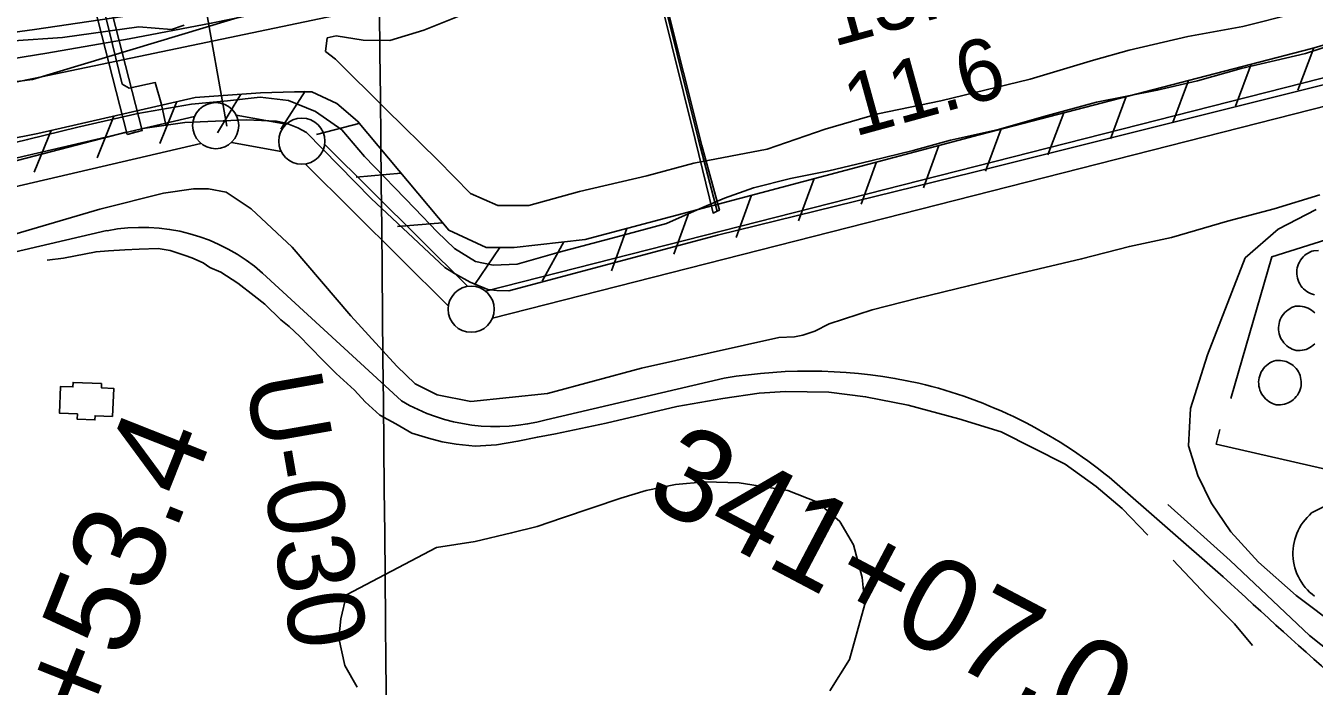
# Model space of a CAD drawing. Extents: x 3625074 to 3663148, y 511451 to 537151.
# Drawn here: x 3639466 to 3640863, y 517652 to 518368 of the extents above; entities that cross this region are included whole.
import ezdxf

# ---------------------------------------------------------------- set-up
doc = ezdxf.new("R2010")
doc.units = 0
for name, color, linetype in [('V-BLDG-OTLN', 7, 'Continuous'), ('V-CHAN-DOCK', 7, 'Continuous'), ('V-DOMW-TANK', 7, 'Continuous'), ('V-FLOD-BASE', 7, 'Continuous'), ('V-GRID-MAJR', 7, 'Continuous'), ('V-LEVE-TOET', 7, 'Continuous'), ('V-RIVR-EDGE', 7, 'Continuous'), ('V-RIVR-RANG', 7, 'Continuous'), ('V-RIVR-RANG-IDEN', 7, 'Continuous'), ('V-ROAD-CNTR', 7, 'Continuous'), ('V-RRAP-FSHR', 7, 'Continuous'), ('V-SITE-OTLN', 7, 'Continuous'), ('V-SITE-VEGE', 7, 'Continuous'), ('V-SURV-IDEN', 7, 'Continuous'), ('V-SURV-LINE', 7, 'Continuous'), ('V-TOPO-DPTH', 7, 'Continuous'), ('V-TOPO-MINR', 7, 'Continuous'), ('V-TOPO-SHOR', 7, 'Continuous'), ('V-TOPO-WATR', 7, 'Continuous'), ('V-UTIL-LINE', 7, 'Continuous')]:
    doc.layers.add(name, color=color, linetype=linetype)

msp = doc.modelspace()

# ---------------------------------------------------------------- linework, layer by layer
at = {"layer": 'V-BLDG-OTLN'}
msp.add_lwpolyline([(3639547.8, 517980), (3639547.6, 517975.4), (3639561.1, 517974.8), (3639559.6, 517944.3), (3639540.8, 517945.1), (3639540.6, 517940.5), (3639521.5, 517941.3), (3639521.7, 517947.1), (3639502.1, 517947.9), (3639503.4, 517976.9), (3639516.7, 517976.3), (3639516.9, 517981.3)], close=True, dxfattribs=at)
at = {"layer": 'V-CHAN-DOCK'}
for points in [[(3640215.5, 518166.8), (3640210.9, 518164.8), (3640191.7, 518244.5), (3640115.3, 518552.2), (3640119.7, 518553.7), (3640198.8, 518238.3), (3640217.9, 518168.2), (3640215.5, 518166.8)], [(3639575.6, 518250.2), (3639532.3, 518420), (3639548.4, 518424.1), (3639591.7, 518254.3), (3639575.6, 518250.2)]]:
    msp.add_lwpolyline(points, dxfattribs=at)
at = {"layer": 'V-DOMW-TANK'}
for points in [[(3640863.2, 518076.2), (3640861, 518076.8), (3640858.9, 518077.6), (3640856.8, 518078.6), (3640854.9, 518079.8), (3640853.1, 518081.1), (3640851.4, 518082.6), (3640849.8, 518084.3), (3640848.5, 518086.1), (3640847.2, 518088), (3640846.2, 518090), (3640845.4, 518092.1), (3640844.7, 518094.2), (3640844.3, 518096.5), (3640844, 518098.7), (3640844, 518101), (3640844.2, 518103.2), (3640844.5, 518105.5), (3640845.1, 518107.6), (3640845.9, 518109.8), (3640846.9, 518111.8), (3640848, 518113.8), (3640849.4, 518115.6), (3640850.9, 518117.3), (3640852.5, 518118.9), (3640854.3, 518120.2), (3640856.2, 518121.5), (3640858.2, 518122.5), (3640860.3, 518123.4), (3640862.4, 518124.1), (3640867.5, 518124.2)], [(3640863.4, 518023), (3640861.8, 518021.5), (3640860.1, 518020.1), (3640858.2, 518019), (3640856.3, 518018), (3640854.2, 518017.1), (3640852.1, 518016.5), (3640850, 518016.1), (3640847.8, 518015.8), (3640845.6, 518015.8), (3640843.4, 518015.9), (3640841.2, 518016.5), (3640839.1, 518017.3), (3640837, 518018.3), (3640835.1, 518019.5), (3640833.3, 518020.8), (3640831.6, 518022.3), (3640830.1, 518024), (3640828.7, 518025.8), (3640827.5, 518027.7), (3640826.4, 518029.7), (3640825.6, 518031.8), (3640824.9, 518034), (3640824.5, 518036.2), (3640824.2, 518038.4), (3640824.2, 518040.7), (3640824.4, 518043), (3640824.7, 518045.2), (3640825.3, 518047.4), (3640826.1, 518049.5), (3640827.1, 518051.5), (3640828.2, 518053.5), (3640829.6, 518055.3), (3640831.1, 518057), (3640832.7, 518058.6), (3640834.5, 518060), (3640836.4, 518061.2), (3640838.4, 518062.3), (3640840.5, 518063.1), (3640842.6, 518063.8), (3640847.7, 518063.9), (3640849.9, 518063.7), (3640852.1, 518063.3), (3640854.2, 518062.6), (3640856.2, 518061.8), (3640858.2, 518060.8), (3640860, 518059.6), (3640861.8, 518058.3), (3640863.4, 518056.8)], [(3640863.2, 517749.4), (3640860.5, 517751.6), (3640857.9, 517753.9), (3640855.5, 517756.3), (3640853.2, 517758.9), (3640851, 517761.6), (3640849.1, 517764.5), (3640847.3, 517767.4), (3640845.7, 517770.5), (3640844.2, 517773.6), (3640843, 517776.9), (3640842, 517780.2), (3640841.1, 517783.5), (3640840.5, 517786.9), (3640840.1, 517790.4), (3640839.8, 517793.8), (3640839.8, 517797.3), (3640840, 517800.7), (3640840.4, 517804.2), (3640841, 517807.6), (3640841.8, 517810.9), (3640842.9, 517814.3), (3640844.1, 517817.5), (3640845.5, 517820.7), (3640847, 517823.7), (3640848.8, 517826.7), (3640850.8, 517829.6), (3640852.9, 517832.3), (3640855.1, 517834.9), (3640857.6, 517837.4), (3640860.1, 517839.7), (3640878.7, 517849.3)]]:
    msp.add_lwpolyline(points, dxfattribs=at)
msp.add_lwpolyline([(3640826.2, 518005.1), (3640828.4, 518004.8), (3640830.5, 518004.4), (3640832.6, 518003.8), (3640834.7, 518002.9), (3640836.6, 518001.9), (3640838.5, 518000.7), (3640840.2, 517999.4), (3640841.9, 517997.9), (3640843.3, 517996.3), (3640844.6, 517994.5), (3640845.8, 517992.6), (3640846.8, 517990.6), (3640847.5, 517988.6), (3640848.1, 517986.5), (3640848.5, 517984.3), (3640848.8, 517982.1), (3640848.8, 517979.9), (3640848.6, 517977.7), (3640848.2, 517975.6), (3640847.6, 517973.4), (3640846.8, 517971.4), (3640845.8, 517969.4), (3640844.7, 517967.5), (3640843.4, 517965.8), (3640841.9, 517964.1), (3640840.3, 517962.6), (3640838.5, 517961.3), (3640836.7, 517960.1), (3640834.7, 517959.1), (3640832.7, 517958.2), (3640830.6, 517957.6), (3640828.4, 517957.2), (3640826.2, 517956.9), (3640824, 517956.9), (3640821.8, 517957), (3640819.6, 517957.6), (3640817.5, 517958.4), (3640815.5, 517959.4), (3640813.6, 517960.6), (3640811.7, 517961.9), (3640810, 517963.5), (3640808.5, 517965.1), (3640807.1, 517966.9), (3640805.9, 517968.8), (3640804.9, 517970.8), (3640804, 517972.9), (3640803.4, 517975.1), (3640802.9, 517977.3), (3640802.7, 517979.6), (3640802.6, 517981.8), (3640802.8, 517984.1), (3640803.2, 517986.3), (3640803.8, 517988.5), (3640804.6, 517990.6), (3640805.5, 517992.7), (3640806.7, 517994.6), (3640808, 517996.4), (3640809.5, 517998.1), (3640811.2, 517999.7), (3640812.9, 518001.1), (3640814.8, 518002.3), (3640816.8, 518003.4), (3640818.9, 518004.2), (3640821.1, 518004.9)], close=True, dxfattribs=at)
at = {"layer": 'V-FLOD-BASE'}
for points in [[(3639840.1, 518180.7), (3639920.2, 518106), (3639930.6, 518099.2), (3639947.4, 518089.8), (3639966.7, 518081.9), (3639976.5, 518080.8), (3639989.5, 518080.4), (3640215.8, 518140.8), (3640493.7, 518209.4), (3640874, 518304.4), (3640950.3, 518325.1), (3640996.3, 518339.2), (3641036.5, 518353.5), (3641226.9, 518436.9), (3641384.5, 518513.8)], [(3639592.5, 518256.6), (3639638.2, 518263.1), (3639704.6, 518266.1), (3639737.7, 518264.4), (3639748.1, 518262.3), (3639760.5, 518257.4), (3639770.1, 518252.4), (3639840.1, 518180.7)], [(3638324.9, 518061.5), (3638500, 518081.6), (3638753.3, 518108.7), (3639059.9, 518145.8), (3639185.8, 518157.3), (3639228.1, 518165.3), (3639429.7, 518214.9), (3639574.5, 518252.6)]]:
    msp.add_lwpolyline(points, dxfattribs=at)
at = {"layer": 'V-GRID-MAJR'}
msp.add_spline([(3639863.3, 516966), (3639803.4, 523023.6), (3639743.5, 529084.3), (3639717.7, 531688.3)], degree=3, dxfattribs=at)
at = {"layer": 'V-LEVE-TOET'}
for points in [[(3640160.4, 518153.5), (3640193.8, 518168.3), (3640223.5, 518181), (3640254.9, 518192.2), (3640294.9, 518202.2), (3640336.6, 518210.8), (3640382.1, 518221.4), (3640427.8, 518232.7), (3640468.6, 518244), (3640519.2, 518255.3), (3640569.7, 518269.5), (3640626.7, 518285.3), (3640692.6, 518298.1), (3640736.4, 518308.1), (3640783.6, 518321.7), (3640853.4, 518338), (3640925.4, 518361.5)], [(3639409.4, 518230.4), (3639467.6, 518244.5), (3639522.2, 518258), (3639587.3, 518272.9), (3639645.5, 518283), (3639684.3, 518286.7), (3639719.7, 518290.5), (3639750.7, 518287.1), (3639779.7, 518275), (3639808.5, 518255), (3639833, 518226.1), (3639887.4, 518169.7), (3639911.9, 518144.6), (3639930.6, 518126.4), (3639953.2, 518112.3), (3639972.6, 518108.4), (3639998.7, 518109.4), (3640044.1, 518122.4), (3640105.4, 518138.8), (3640160.4, 518153.5)], [(3639453.6, 518141.9), (3639546.1, 518169.1), (3639615, 518186.5), (3639647.6, 518191.2), (3639663.8, 518191.1), (3639683, 518187.5), (3639710.1, 518169.3), (3639754.5, 518128), (3639818.1, 518053.3), (3639867.9, 517998.9), (3639888, 517979.6), (3639911.8, 517967.8), (3639948.3, 517960.6), (3640031.3, 517969.2), (3640133.4, 517996.6), (3640282.3, 518030.1), (3640299.4, 518030.5)], [(3640299.4, 518030.5), (3640308.5, 518032.3), (3640321.4, 518036.9), (3640336.7, 518044.7), (3640383.6, 518059.8), (3640433, 518072.7), (3640488, 518085.8), (3640544.7, 518099.7), (3640610.6, 518115.1), (3640662.4, 518128.7), (3640708.1, 518138.5), (3640768.9, 518156), (3640819.3, 518169.3), (3640868.9, 518184.5)]]:
    msp.add_lwpolyline(points, dxfattribs=at)
at = {"layer": 'V-RIVR-EDGE'}
msp.add_lwpolyline([(3639452.5, 518351.7), (3639505.3, 518355.2), (3639588.2, 518367), (3639623.6, 518363.9), (3639637.4, 518368.6)], dxfattribs=at)
at = {"layer": 'V-RIVR-RANG'}
msp.add_line((3639683.8, 518259.1), (3639573, 518882.3), dxfattribs=at)
at = {"layer": 'V-ROAD-CNTR'}
for points in [[(3638977.2, 518013.1), (3639312, 518089.6), (3639553.7, 518145.8)], [(3639722.4, 518099.8), (3639873, 517961.2)], [(3640029.9, 517940.8), (3640223, 517985.8)], [(3640640.5, 517878.3), (3640764.2, 517770.4)]]:
    msp.add_lwpolyline(points, dxfattribs=at)
for centre, radius, start, end in [((3639591.6, 517952), 197.4, 48.478, 101.0504), ((3640314.6, 517444.1), 549.4, 77.423, 99.596), ((3640314.5, 517478.9), 515.6, 50.7765, 76.5662), ((3639975.4, 518135.6), 202.3, 239.5637, 285.6267), ((3646478.1, 523964), 8426.7, 227.30707, 228.5106)]:
    msp.add_arc(centre, radius, start, end, dxfattribs=at)
at = {"layer": 'V-RRAP-FSHR'}
for p, q in [((3640862.3, 518344), (3640845.2, 518298.2)), ((3640794.5, 518326.4), (3640777.4, 518280.7)), ((3640726.7, 518308.8), (3640709.7, 518263.1)), ((3639698.9, 518293.7), (3639673.7, 518251.8)), ((3639768.8, 518296.9), (3639742.2, 518255.9)), ((3640659, 518291.3), (3640641.9, 518245.5)), ((3639629.5, 518285.7), (3639611.1, 518240.5)), ((3639561.3, 518270.1), (3639542.9, 518224.9)), ((3639828.1, 518262.2), (3639780.8, 518250.1)), ((3640591.2, 518273.7), (3640574.1, 518228)), ((3639493, 518254.5), (3639474.7, 518209.3)), ((3640523.5, 518256.1), (3640506.4, 518210.4)), ((3640455.8, 518238.3), (3640439, 518192.4)), ((3640388.1, 518220.3), (3640371.4, 518174.4)), ((3639872.6, 518208.1), (3639824, 518203.9)), ((3640320.5, 518202.3), (3640303.7, 518156.4)), ((3640252.8, 518184.3), (3640236.1, 518138.4)), ((3640185.2, 518166.3), (3640168.4, 518120.4)), ((3639917.6, 518154.4), (3639868.9, 518150.2)), ((3640117.5, 518148.3), (3640100.8, 518102.4)), ((3639979.6, 518127.6), (3639952.1, 518087.2)), ((3640049.3, 518133.7), (3640025.8, 518090.9))]:
    msp.add_line(p, q, dxfattribs=at)
for points in [[(3638360.7, 518107.6), (3638611.2, 518126.5), (3638961.4, 518161.8), (3639165.9, 518189.2), (3639478.8, 518251.3), (3639649.3, 518290.2), (3639720.3, 518295.1), (3639757.2, 518296.5), (3639776, 518296.2), (3639803.1, 518283.7), (3639825.2, 518264.7), (3639924.3, 518146.4), (3639964.9, 518127.4), (3639995.4, 518127.7), (3640072.3, 518136.2), (3640499.4, 518249.9), (3640860.3, 518343.5), (3641007.5, 518386.2), (3641189, 518473.4), (3641393, 518563)], [(3637231, 518312.6), (3637633.2, 518236.6), (3637834.7, 518218.4), (3638037, 518209.4), (3638275.4, 518210.8), (3638444.3, 518216), (3638635.8, 518243), (3638873.1, 518265.8), (3639014.4, 518264.1), (3639255.4, 518281.9), (3639473, 518309.7), (3639876.1, 518431.4)]]:
    msp.add_lwpolyline(points, dxfattribs=at)
at = {"layer": 'V-SITE-OTLN'}
msp.add_lwpolyline([(3640889.8, 517715.2), (3640843.3, 517750.1), (3640802.4, 517786.2), (3640772.6, 517819.1), (3640751.2, 517850.5), (3640736.6, 517880.2), (3640726.4, 517912.6), (3640728.9, 517953.1), (3640747.3, 518011.2), (3640788, 518116.3), (3640823.8, 518147.4), (3640865, 518168.6)], dxfattribs=at)
at = {"layer": 'V-SITE-VEGE'}
for points in [[(3640843, 518381.6), (3640785.6, 518367.3), (3640725.9, 518356.3), (3640662.2, 518341.6), (3640623.4, 518330.8), (3640555, 518310), (3640457.9, 518286.7), (3640389.6, 518272.5), (3640332.7, 518255.8), (3640269.8, 518234), (3640190.1, 518219.1), (3640139.1, 518205.1), (3640066, 518188.4), (3640011, 518173), (3639977.4, 518173.1), (3639947.8, 518186.2), (3639912.5, 518222.4), (3639856.5, 518277.3), (3639801.6, 518331.6), (3639790.7, 518340.1), (3639792.5, 518354.9), (3639802.4, 518357), (3639831.4, 518352.4), (3639860.3, 518352.2), (3639897.4, 518363.3), (3639948.1, 518383.6)], [(3639825, 517650.7), (3639811.6, 517674.2), (3639805.3, 517703.8), (3639807.2, 517724.7), (3639813.5, 517751), (3639910.9, 517802.3), (3639953, 517808.8), (3639992.4, 517818), (3640020.2, 517824.9), (3640047.8, 517834.2), (3640110.9, 517855.7), (3640138.4, 517864), (3640170.2, 517870.5), (3640202.3, 517873.5), (3640239.4, 517872.5), (3640291.9, 517864.1), (3640324.4, 517851.3), (3640348.4, 517830.4), (3640363.1, 517805.1), (3640372.7, 517769.6), (3640375.6, 517740.9), (3640359.1, 517680.9), (3640337.7, 517646.8)]]:
    msp.add_lwpolyline(points, dxfattribs=at)
at = {"layer": 'V-SURV-LINE'}
for points in [[(3639964.2, 518080.1), (3640987.8, 518340.7)], [(3640995.2, 518311.6), (3639971.6, 518051)], [(3639204.7, 518166.3), (3639648.7, 518269.7)], [(3639693.9, 518270.9), (3639748, 518261.2)], [(3639655.5, 518240.5), (3639211.5, 518137.1)], [(3639742.7, 518231.7), (3639688.6, 518241.4)], [(3639789.7, 518239.5), (3639945, 518085.4)], [(3639923.8, 518064.1), (3639768.6, 518218.2)]]:
    msp.add_lwpolyline(points, dxfattribs=at)
for centre in [(3639671.6, 518259.7), (3639765, 518242.9), (3639948.6, 518060.6)]:
    msp.add_circle(centre, 25, dxfattribs=at)
at = {"layer": 'V-TOPO-DPTH'}
for points in [[(3641562.9, 518893), (3640452.6, 518518.4), (3640446.8, 518516.4), (3640440.9, 518514.6), (3640435, 518512.9), (3640429.1, 518511.2), (3640423.1, 518509.6), (3640417.1, 518508.2), (3640411.1, 518506.8), (3640405.1, 518505.5), (3639474.1, 518310.8), (3639432.7, 518302.4)], [(3638396.8, 518274.7), (3638538.3, 518279.5), (3638679.6, 518287.2), (3638820.8, 518297), (3639200.6, 518327.1), (3639207.6, 518327.8), (3639214.6, 518328.5), (3639221.5, 518329.3), (3639228.5, 518330.2), (3639475.1, 518363.8), (3639605.1, 518383.2), (3639734.7, 518404.6), (3639863.7, 518429.3), (3639992.4, 518456), (3640351.9, 518535.3), (3640379, 518541.6), (3640406, 518548.3), (3640432.8, 518555.5), (3640459.6, 518563.1), (3640587, 518600.8), (3640677.1, 518628.3), (3640766.9, 518656.9), (3640856.1, 518687.2), (3640945, 518718.5)], [(3640945, 518718.5), (3640856.1, 518687.2), (3640766.9, 518656.9), (3640677.1, 518628.3), (3640587, 518600.8), (3640459.6, 518563.1), (3640432.8, 518555.5), (3640406, 518548.3), (3640379, 518541.6), (3640351.9, 518535.3), (3639992.4, 518456), (3639863.7, 518429.3), (3639734.7, 518404.6), (3639605.1, 518383.2), (3639475.1, 518363.8), (3639228.5, 518330.2)]]:
    msp.add_lwpolyline(points, dxfattribs=at)
at = {"layer": 'V-TOPO-MINR'}
for points in [[(3639399, 518324), (3639488.5, 518338.3), (3639577.7, 518353.7), (3639666.7, 518370.7), (3639755.5, 518388.9), (3640338.5, 518513.8), (3640374.8, 518521.9), (3640410.9, 518530.5), (3640446.9, 518539.8), (3640482.7, 518549.6), (3640506.7, 518556.4), (3640554.3, 518570.3), (3640601.8, 518584.8), (3640648.9, 518600.2), (3640695.9, 518616.1), (3641536.3, 518909.3)], [(3639432.7, 518302.4), (3639474.1, 518310.8), (3640405.1, 518505.5), (3640411.1, 518506.8), (3640417.1, 518508.2), (3640423.1, 518509.6), (3640429.1, 518511.2), (3640435, 518512.9), (3640440.9, 518514.6), (3640446.8, 518516.4), (3640452.6, 518518.4), (3641562.9, 518893)]]:
    msp.add_lwpolyline(points, dxfattribs=at)
at = {"layer": 'V-TOPO-SHOR'}
for points in [[(3639488.9, 518113.9), (3639506.4, 518116), (3639541.9, 518122.9), (3639555.3, 518124), (3639573, 518125), (3639588.6, 518125.9), (3639609.1, 518126.5), (3639622.4, 518124.2), (3639638.5, 518118.9), (3639645.8, 518116.3), (3639658.1, 518111), (3639665.3, 518106), (3639677, 518100.7), (3639695.6, 518089), (3639713.2, 518075), (3639724.9, 518066.1), (3639742.3, 518049.2), (3639751.4, 518041.8), (3639762.7, 518031), (3639773.4, 518020.3), (3639788.8, 518004.3), (3639802.4, 517991), (3639822.2, 517973), (3639833.7, 517960.1)], [(3639833.7, 517960.1), (3639849.7, 517945.6), (3639866.9, 517936.4), (3639884.4, 517926.1), (3639902.2, 517920.8), (3639917.2, 517916.9), (3639932.5, 517914.1), (3639952.9, 517912.2), (3639976.2, 517913.7), (3639999.4, 517917.5), (3640020.5, 517922), (3640040.2, 517925.5), (3640095, 517937.1), (3640171.5, 517955), (3640221.5, 517963.7), (3640261.1, 517969.5), (3640289.5, 517971.4), (3640336.4, 517970.8), (3640376.3, 517965.7), (3640422.7, 517956.4), (3640477.6, 517941.6), (3640523.4, 517927.6), (3640592.9, 517892.5), (3640626.6, 517868.5), (3640654.8, 517844.6), (3640682.4, 517815.5)], [(3640704.2, 517849), (3640771.6, 517788), (3640857.6, 517706.9), (3640915.7, 517660.7), (3640973.4, 517629.9), (3641032.6, 517606.5), (3641064.7, 517597.9)], [(3640709.9, 517788.5), (3640746.5, 517749.8), (3640776.6, 517719.3), (3640796.1, 517696)]]:
    msp.add_lwpolyline(points, dxfattribs=at)
at = {"layer": 'V-TOPO-WATR'}
msp.add_lwpolyline([(3639228.5, 518330.2), (3639475.1, 518363.8), (3639605.1, 518383.2), (3639734.7, 518404.6), (3639863.7, 518429.3), (3639992.4, 518456), (3640351.9, 518535.3), (3640379, 518541.6), (3640406, 518548.3), (3640432.8, 518555.5), (3640459.6, 518563.1), (3640587, 518600.8), (3640677.1, 518628.3), (3640766.9, 518656.9), (3640856.1, 518687.2), (3640945, 518718.5)], dxfattribs=at)
at = {"layer": 'V-UTIL-LINE'}
msp.add_line((3639584.9, 518253.1), (3639577.3, 518250.4), dxfattribs=at)
for points in [[(3640215.5, 518166.8), (3640195.1, 518244.4), (3640149, 518430.5), (3640117.8, 518552.9)], [(3639577.6, 518300.3), (3639570, 518304.8), (3639542.1, 518420.7)], [(3640772.5, 517963.9), (3640816.9, 518117.5), (3640882.2, 518138.1), (3640889.3, 518148.8), (3640885.5, 518162.2), (3641098.1, 518220.3), (3641092.9, 518233.9), (3641070.1, 518288.1), (3641049.2, 518337.9)], [(3639577.6, 518300.3), (3639606.1, 518306.4), (3639612.9, 518282.7), (3639617.6, 518260.5)], [(3640760.6, 517930.1), (3640756.6, 517914.1), (3641085.1, 517839.1), (3641087.5, 517849.5), (3641147.1, 517834.6), (3641156.9, 517832.9), (3641161.1, 517832.8), (3641228.4, 517816.2), (3641227.5, 517810.6), (3641264.3, 517802.6), (3641420.1, 518239.9), (3641423, 518248.2)]]:
    msp.add_lwpolyline(points, dxfattribs=at)

# ---------------------------------------------------------------- texts
at = {"layer": 'V-RIVR-RANG'}
for s, p in [('13.1', (3640341.6, 518345.1)), ('11.6', (3640364.3, 518247.6))]:
    msp.add_text(s, height=67, rotation=15.3883, dxfattribs=at).set_placement(p)
at = {"layer": 'V-RIVR-RANG-IDEN'}
msp.add_text('U-030', height=83, rotation=279.9413, dxfattribs=at).set_placement((3639703.5, 517984.9))
at = {"layer": 'V-SURV-IDEN'}
for s, rotation, p in [('337+53.4', 68.3753, (3639461.6, 517399.6)), ('341+07.0', 332.2026, (3640134.1, 517853))]:
    msp.add_text(s, height=100, rotation=rotation, dxfattribs=at).set_placement(p)

doc.saveas('drawing.dxf')
